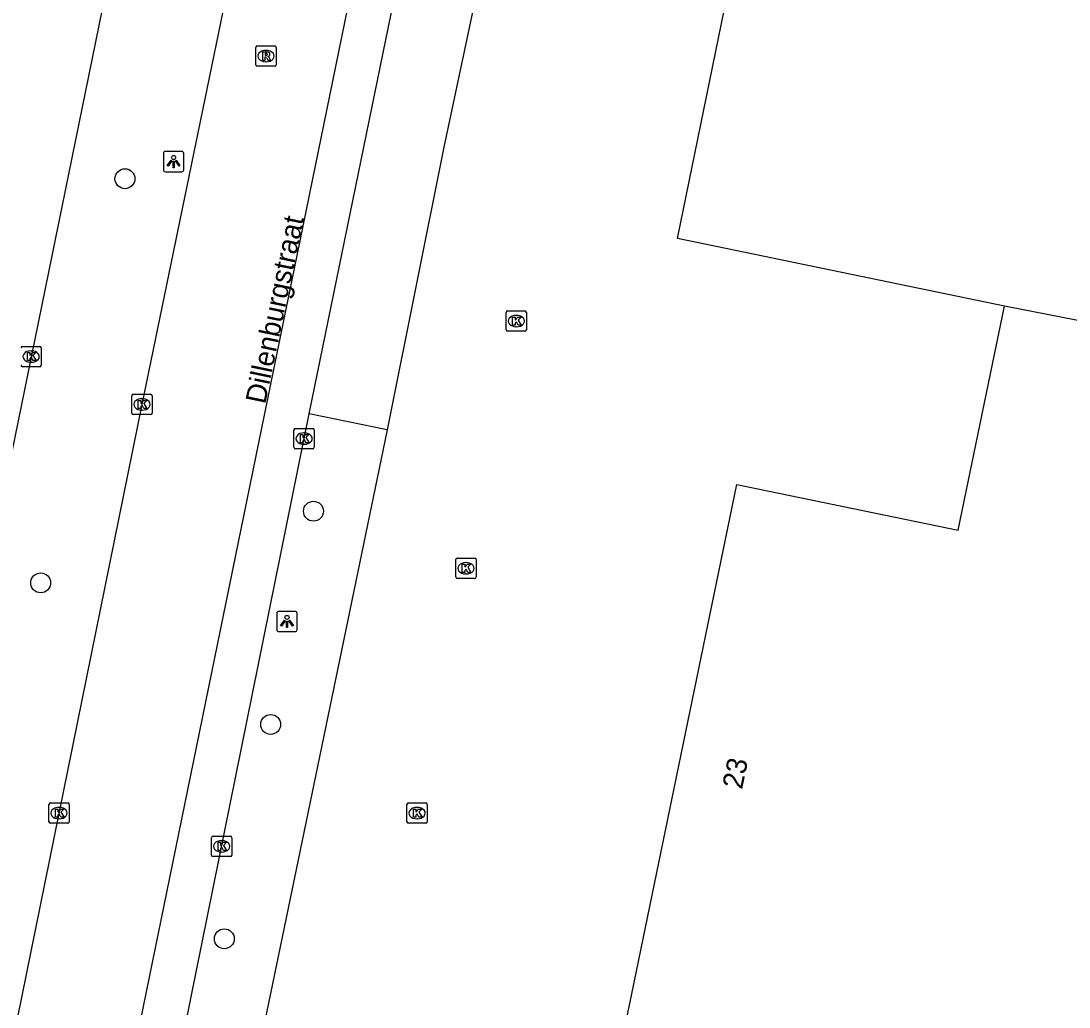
# Model space of a CAD drawing. Extents: x 157692 to 159670, y 381454 to 383289.
# Drawn here: x 158528.9 to 158580.5, y 382137.6 to 382186.1 of the extents above; entities that cross this region are included whole.
import ezdxf

# ---------------------------------------------------------------- set-up
doc = ezdxf.new("R2010")
doc.units = 0
for name, color, linetype in [('IMGEO_Boom', 7, 'Continuous'), ('IMGEO_Kolk', 7, 'Continuous'), ('IMGEO_Lichtpunt', 7, 'Continuous'), ('IMGEO_Openbare_ruimte_label', 7, 'Continuous'), ('IMGEO_Pand', 7, 'Continuous'), ('IMGEO_Pand_nummerreeks', 7, 'Continuous'), ('IMGEO_Rijbaan_lokaal_gesloten', 7, 'Continuous'), ('IMGEO_Rijbaan_lokaal_open', 7, 'Continuous'), ('IMGEO_Rioolput', 7, 'Continuous'), ('IMGEO_Voetpad_open', 7, 'Continuous')]:
    doc.layers.add(name, color=color, linetype=linetype)

msp = doc.modelspace()

# ---------------------------------------------------------------- linework, layer by layer
at = {"layer": 'IMGEO_Boom'}
for centre in [(158534.04, 382178.306), (158543.31, 382161.961), (158529.896, 382158.438), (158541.206, 382151.477), (158538.925, 382140.939)]:
    msp.add_circle(centre, 0.489, dxfattribs=at)
at = {"layer": 'IMGEO_Kolk'}
for p, q in [((158552.783, 382170.882), (158552.783, 382171.734)), ((158552.858, 382171.808), (158553.71, 382171.808)), ((158553.271, 382171.588), (158553.296, 382171.588)), ((158553.784, 382171.734), (158553.784, 382170.882)), ((158553.294, 382171.028), (158553.269, 382171.028)), ((158553.71, 382170.808), (158552.858, 382170.808)), ((158529.001, 382170.064), (158529.853, 382170.064)), ((158529.414, 382169.844), (158529.439, 382169.844)), ((158529.927, 382169.99), (158529.927, 382169.138)), ((158529.853, 382169.064), (158529.001, 382169.064)), ((158529.437, 382169.284), (158529.412, 382169.284)), ((158534.376, 382166.784), (158534.376, 382167.636)), ((158534.451, 382167.71), (158535.303, 382167.71)), ((158534.864, 382167.49), (158534.889, 382167.49)), ((158535.377, 382167.636), (158535.377, 382166.784)), ((158534.887, 382166.93), (158534.862, 382166.93)), ((158535.303, 382166.71), (158534.451, 382166.71)), ((158542.351, 382165.104), (158542.351, 382165.956)), ((158542.426, 382166.03), (158543.278, 382166.03)), ((158543.352, 382165.956), (158543.352, 382165.104)), ((158542.839, 382165.81), (158542.864, 382165.81)), ((158543.278, 382165.03), (158542.426, 382165.03)), ((158542.862, 382165.25), (158542.837, 382165.25)), ((158550.31, 382158.728), (158550.31, 382159.58)), ((158550.385, 382159.654), (158551.237, 382159.654)), ((158550.798, 382159.434), (158550.823, 382159.434)), ((158551.311, 382159.58), (158551.311, 382158.728)), ((158551.237, 382158.654), (158550.385, 382158.654)), ((158550.821, 382158.874), (158550.796, 382158.874)), ((158530.299, 382146.692), (158530.299, 382147.544)), ((158530.374, 382147.618), (158531.226, 382147.618)), ((158530.787, 382147.398), (158530.812, 382147.398)), ((158531.3, 382147.544), (158531.3, 382146.692)), ((158547.907, 382146.691), (158547.907, 382147.543)), ((158547.982, 382147.617), (158548.834, 382147.617)), ((158548.395, 382147.397), (158548.42, 382147.397)), ((158548.908, 382147.543), (158548.908, 382146.691)), ((158530.81, 382146.838), (158530.785, 382146.838)), ((158548.418, 382146.837), (158548.393, 382146.837)), ((158531.226, 382146.618), (158530.374, 382146.618)), ((158548.834, 382146.617), (158547.982, 382146.617)), ((158538.297, 382145.058), (158538.297, 382145.91)), ((158538.372, 382145.984), (158539.224, 382145.984)), ((158539.298, 382145.91), (158539.298, 382145.058)), ((158538.785, 382145.764), (158538.81, 382145.764)), ((158539.224, 382144.984), (158538.372, 382144.984)), ((158538.808, 382145.204), (158538.783, 382145.204))]:
    msp.add_line(p, q, dxfattribs=at)
for points in [[(158552.783, 382170.882), (158552.783, 382171.734)], [(158552.858, 382171.808), (158553.71, 382171.808)], [(158553.784, 382171.734), (158553.784, 382170.882)], [(158553.104, 382171.508), (158553.227, 382171.508), (158553.227, 382171.357), (158553.357, 382171.508), (158553.521, 382171.508), (158553.375, 382171.357), (158553.528, 382171.108), (158553.376, 382171.108), (158553.291, 382171.272), (158553.227, 382171.205), (158553.227, 382171.108), (158553.104, 382171.108), (158553.104, 382171.508)], [(158553.71, 382170.808), (158552.858, 382170.808)], [(158529.001, 382170.064), (158529.853, 382170.064)], [(158529.247, 382169.764), (158529.37, 382169.764), (158529.37, 382169.613), (158529.5, 382169.764), (158529.664, 382169.764), (158529.518, 382169.613), (158529.671, 382169.364), (158529.519, 382169.364), (158529.434, 382169.528), (158529.37, 382169.461), (158529.37, 382169.364), (158529.247, 382169.364), (158529.247, 382169.764)], [(158529.927, 382169.99), (158529.927, 382169.138)], [(158529.853, 382169.064), (158529.001, 382169.064)], [(158534.376, 382166.784), (158534.376, 382167.636)], [(158534.451, 382167.71), (158535.303, 382167.71)], [(158535.377, 382167.636), (158535.377, 382166.784)], [(158534.697, 382167.41), (158534.82, 382167.41), (158534.82, 382167.259), (158534.95, 382167.41), (158535.114, 382167.41), (158534.968, 382167.259), (158535.121, 382167.01), (158534.969, 382167.01), (158534.884, 382167.174), (158534.82, 382167.107), (158534.82, 382167.01), (158534.697, 382167.01), (158534.697, 382167.41)], [(158535.303, 382166.71), (158534.451, 382166.71)], [(158542.351, 382165.104), (158542.351, 382165.956)], [(158542.426, 382166.03), (158543.278, 382166.03)], [(158543.352, 382165.956), (158543.352, 382165.104)], [(158542.672, 382165.73), (158542.795, 382165.73), (158542.795, 382165.579), (158542.925, 382165.73), (158543.089, 382165.73), (158542.943, 382165.579), (158543.096, 382165.33), (158542.944, 382165.33), (158542.859, 382165.494), (158542.795, 382165.427), (158542.795, 382165.33), (158542.672, 382165.33), (158542.672, 382165.73)], [(158543.278, 382165.03), (158542.426, 382165.03)], [(158550.31, 382158.728), (158550.31, 382159.58)], [(158550.385, 382159.654), (158551.237, 382159.654)], [(158550.631, 382159.354), (158550.754, 382159.354), (158550.754, 382159.203), (158550.884, 382159.354), (158551.048, 382159.354), (158550.902, 382159.203), (158551.055, 382158.954), (158550.903, 382158.954), (158550.818, 382159.118), (158550.754, 382159.051), (158550.754, 382158.954), (158550.631, 382158.954), (158550.631, 382159.354)], [(158551.311, 382159.58), (158551.311, 382158.728)], [(158551.237, 382158.654), (158550.385, 382158.654)], [(158530.299, 382146.692), (158530.299, 382147.544)], [(158530.374, 382147.618), (158531.226, 382147.618)], [(158530.62, 382147.318), (158530.743, 382147.318), (158530.743, 382147.167), (158530.873, 382147.318), (158531.037, 382147.318), (158530.891, 382147.167), (158531.044, 382146.918), (158530.892, 382146.918), (158530.807, 382147.082), (158530.743, 382147.015), (158530.743, 382146.918), (158530.62, 382146.918), (158530.62, 382147.318)], [(158531.3, 382147.544), (158531.3, 382146.692)], [(158547.907, 382146.691), (158547.907, 382147.543)], [(158547.982, 382147.617), (158548.834, 382147.617)], [(158548.228, 382147.317), (158548.351, 382147.317), (158548.351, 382147.166), (158548.481, 382147.317), (158548.645, 382147.317), (158548.499, 382147.166), (158548.652, 382146.917), (158548.5, 382146.917), (158548.415, 382147.081), (158548.351, 382147.014), (158548.351, 382146.917), (158548.228, 382146.917), (158548.228, 382147.317)], [(158548.908, 382147.543), (158548.908, 382146.691)], [(158531.226, 382146.618), (158530.374, 382146.618)], [(158548.834, 382146.617), (158547.982, 382146.617)], [(158538.297, 382145.058), (158538.297, 382145.91)], [(158538.372, 382145.984), (158539.224, 382145.984)], [(158539.298, 382145.91), (158539.298, 382145.058)], [(158538.618, 382145.684), (158538.741, 382145.684), (158538.741, 382145.533), (158538.871, 382145.684), (158539.035, 382145.684), (158538.889, 382145.533), (158539.042, 382145.284), (158538.89, 382145.284), (158538.805, 382145.448), (158538.741, 382145.381), (158538.741, 382145.284), (158538.618, 382145.284), (158538.618, 382145.684)], [(158539.224, 382144.984), (158538.372, 382144.984)]]:
    msp.add_lwpolyline(points, dxfattribs=at)
for centre, start, end in [((158552.86, 382171.732), 91.552, 178.448), ((158552.86, 382171.732), 91.552, 178.448), ((158553.708, 382171.732), 1.552, 88.448), ((158553.708, 382171.732), 1.552, 88.448), ((158552.86, 382170.884), 181.552, 268.448), ((158552.86, 382170.884), 181.552, 268.448), ((158553.708, 382170.884), 271.552, 358.448), ((158553.708, 382170.884), 271.552, 358.448), ((158529.003, 382169.988), 91.552, 178.448), ((158529.003, 382169.988), 91.552, 178.448), ((158529.851, 382169.988), 1.552, 88.448), ((158529.851, 382169.988), 1.552, 88.448), ((158529.003, 382169.14), 181.552, 268.448), ((158529.003, 382169.14), 181.552, 268.448), ((158529.851, 382169.14), 271.552, 358.448), ((158529.851, 382169.14), 271.552, 358.448), ((158534.453, 382167.634), 91.552, 178.448), ((158534.453, 382167.634), 91.552, 178.448), ((158535.301, 382167.634), 1.552, 88.448), ((158535.301, 382167.634), 1.552, 88.448), ((158534.453, 382166.786), 181.552, 268.448), ((158534.453, 382166.786), 181.552, 268.448), ((158535.301, 382166.786), 271.552, 358.448), ((158535.301, 382166.786), 271.552, 358.448), ((158542.428, 382165.954), 91.552, 178.448), ((158542.428, 382165.954), 91.552, 178.448), ((158543.276, 382165.954), 1.552, 88.448), ((158543.276, 382165.954), 1.552, 88.448), ((158542.428, 382165.106), 181.552, 268.448), ((158542.428, 382165.106), 181.552, 268.448), ((158543.276, 382165.106), 271.552, 358.448), ((158543.276, 382165.106), 271.552, 358.448), ((158550.387, 382159.578), 91.552, 178.448), ((158550.387, 382159.578), 91.552, 178.448), ((158551.235, 382159.578), 1.552, 88.448), ((158551.235, 382159.578), 1.552, 88.448), ((158550.387, 382158.73), 181.552, 268.448), ((158550.387, 382158.73), 181.552, 268.448), ((158551.235, 382158.73), 271.552, 358.448), ((158551.235, 382158.73), 271.552, 358.448), ((158530.376, 382147.542), 91.552, 178.448), ((158530.376, 382147.542), 91.552, 178.448), ((158531.224, 382147.542), 1.552, 88.448), ((158531.224, 382147.542), 1.552, 88.448), ((158547.984, 382147.541), 91.552, 178.448), ((158547.984, 382147.541), 91.552, 178.448), ((158548.832, 382147.541), 1.552, 88.448), ((158548.832, 382147.541), 1.552, 88.448), ((158530.376, 382146.694), 181.552, 268.448), ((158530.376, 382146.694), 181.552, 268.448), ((158531.224, 382146.694), 271.552, 358.448), ((158531.224, 382146.694), 271.552, 358.448), ((158547.984, 382146.693), 181.552, 268.448), ((158547.984, 382146.693), 181.552, 268.448), ((158548.832, 382146.693), 271.552, 358.448), ((158548.832, 382146.693), 271.552, 358.448), ((158538.374, 382145.908), 91.552, 178.448), ((158538.374, 382145.908), 91.552, 178.448), ((158539.222, 382145.908), 1.552, 88.448), ((158539.222, 382145.908), 1.552, 88.448), ((158538.374, 382145.06), 181.552, 268.448), ((158538.374, 382145.06), 181.552, 268.448), ((158539.222, 382145.06), 271.552, 358.448), ((158539.222, 382145.06), 271.552, 358.448)]:
    msp.add_arc(centre, 0.0765, start, end, dxfattribs=at)
for centre, major_axis, ratio, start_param, end_param in [((158553.27, 382171.308), (-0.387, 0.002), 0.722429, 4.712389, 7.853982), ((158553.295, 382171.308), (-0.39, 0.002), 0.717154, 1.570796, 4.712389), ((158529.413, 382169.564), (-0.387, 0.002), 0.722429, 4.712389, 7.853982), ((158529.438, 382169.564), (-0.39, 0.002), 0.717154, 1.570796, 4.712389), ((158534.863, 382167.21), (-0.387, 0.002), 0.722429, 4.712389, 7.853982), ((158534.888, 382167.21), (-0.39, 0.002), 0.717154, 1.570796, 4.712389), ((158542.838, 382165.53), (-0.387, 0.002), 0.722429, 4.712389, 7.853982), ((158542.863, 382165.53), (-0.39, 0.002), 0.717154, 1.570796, 4.712389), ((158550.797, 382159.154), (-0.387, 0.002), 0.722429, 4.712389, 7.853982), ((158550.822, 382159.154), (-0.39, 0.002), 0.717154, 1.570796, 4.712389), ((158530.786, 382147.118), (-0.387, 0.002), 0.722429, 4.712389, 7.853982), ((158530.811, 382147.118), (-0.39, 0.002), 0.717154, 1.570796, 4.712389), ((158548.394, 382147.117), (-0.387, 0.002), 0.722429, 4.712389, 7.853982), ((158548.419, 382147.117), (-0.39, 0.002), 0.717154, 1.570796, 4.712389), ((158538.784, 382145.484), (-0.387, 0.002), 0.722429, 4.712389, 7.853982), ((158538.809, 382145.484), (-0.39, 0.002), 0.717154, 1.570796, 4.712389)]:
    msp.add_ellipse(centre, major_axis=major_axis, ratio=ratio, start_param=start_param, end_param=end_param, dxfattribs=at)
at = {"layer": 'IMGEO_Lichtpunt'}
for p, q in [((158535.933, 382179.553), (158535.933, 382178.746)), ((158535.933, 382179.553), (158535.933, 382178.746)), ((158536.835, 382179.648), (158536.027, 382179.648)), ((158536.835, 382179.648), (158536.027, 382179.648)), ((158536.929, 382178.746), (158536.929, 382179.553)), ((158536.929, 382178.746), (158536.929, 382179.553)), ((158536.027, 382178.652), (158536.835, 382178.652)), ((158536.027, 382178.652), (158536.835, 382178.652)), ((158541.51, 382156.942), (158541.51, 382156.135)), ((158541.51, 382156.942), (158541.51, 382156.135)), ((158542.412, 382157.037), (158541.604, 382157.037)), ((158542.412, 382157.037), (158541.604, 382157.037)), ((158542.506, 382156.135), (158542.506, 382156.942)), ((158542.506, 382156.135), (158542.506, 382156.942)), ((158541.604, 382156.041), (158542.412, 382156.041)), ((158541.604, 382156.041), (158542.412, 382156.041))]:
    msp.add_line(p, q, dxfattribs=at)
for points in [[(158536.307, 382179.217), (158536.346, 382179.189), (158536.158, 382178.927), (158536.12, 382178.954), (158536.307, 382179.217)], [(158536.409, 382179.169), (158536.456, 382179.169), (158536.456, 382178.847), (158536.409, 382178.847), (158536.409, 382179.169)], [(158536.519, 382179.189), (158536.557, 382179.216), (158536.744, 382178.954), (158536.705, 382178.926), (158536.519, 382179.189)], [(158541.884, 382156.606), (158541.923, 382156.578), (158541.735, 382156.316), (158541.697, 382156.343), (158541.884, 382156.606)], [(158542.096, 382156.578), (158542.134, 382156.605), (158542.321, 382156.343), (158542.282, 382156.315), (158542.096, 382156.578)], [(158541.986, 382156.558), (158542.033, 382156.558), (158542.033, 382156.236), (158541.986, 382156.236), (158541.986, 382156.558)]]:
    msp.add_lwpolyline(points, dxfattribs=at)
for centre in [(158536.432, 382179.351), (158542.009, 382156.74)]:
    msp.add_circle(centre, 0.0994, dxfattribs=at)
for centre, start, end in [((158536.027, 382179.553), 90, 180), ((158536.027, 382179.553), 90, 180), ((158536.835, 382179.553), 0, 90), ((158536.835, 382179.553), 0, 90), ((158536.027, 382178.746), 180, 270), ((158536.027, 382178.746), 180, 270), ((158536.835, 382178.746), 270, 0), ((158536.835, 382178.746), 270, 360), ((158541.604, 382156.942), 90, 180), ((158541.604, 382156.942), 90, 180), ((158542.412, 382156.942), 0, 90), ((158542.412, 382156.942), 0, 90), ((158541.604, 382156.135), 180, 270), ((158541.604, 382156.135), 180, 270), ((158542.412, 382156.135), 270, 0), ((158542.412, 382156.135), 270, 360)]:
    msp.add_arc(centre, 0.0946, start, end, dxfattribs=at)
at = {"layer": 'IMGEO_Pand'}
for points in [[(158577.294, 382172.047), (158561.216, 382175.361), (158565.247, 382195.087), (158556.948, 382196.783), (158558.961, 382206.635)], [(158563.223, 382131.236), (158563.315, 382131.7), (158554.772, 382133.456), (158554.818, 382133.659), (158556.568, 382133.298), (158557.225, 382136.428), (158558.548, 382136.172), (158564.131, 382163.272), (158575.023, 382161.028), (158577.294, 382172.047)], [(158617.909, 382164.108), (158577.294, 382172.047)]]:
    msp.add_lwpolyline(points, dxfattribs=at)
at = {"layer": 'IMGEO_Rijbaan_lokaal_gesloten'}
for points in [[(158522.982, 382137.975), (158549.349, 382267.06), (158553.124, 382285.066), (158561.45, 382326.139), (158561.609, 382326.746), (158561.897, 382327.314), (158562.266, 382327.772), (158562.742, 382328.162), (158563.281, 382328.442), (158563.854, 382328.604), (158564.425, 382328.647), (158564.939, 382328.591), (158565.051, 382328.557)], [(158566.644, 382322.187), (158547.202, 382227.455), (158542.075, 382202.135), (158534.877, 382167.21), (158528.747, 382136.998)], [(158563.237, 382275.98), (158554.178, 382231.666), (158544.988, 382186.707), (158534.64, 382136.161)], [(158543.098, 382166.746), (158549.561, 382198.266)], [(158537.008, 382136.63), (158543.098, 382166.746)]]:
    msp.add_lwpolyline(points, dxfattribs=at)
at = {"layer": 'IMGEO_Rijbaan_lokaal_open'}
for points in [[(158553.461, 382197.47), (158549.725, 382179.858), (158546.937, 382165.963)], [(158546.937, 382165.963), (158543.098, 382166.746)]]:
    msp.add_lwpolyline(points, dxfattribs=at)
at = {"layer": 'IMGEO_Rioolput'}
for p, q in [((158540.475, 382183.91), (158540.475, 382184.762)), ((158540.55, 382184.836), (158541.402, 382184.836)), ((158540.963, 382184.616), (158540.988, 382184.616)), ((158541.476, 382184.762), (158541.476, 382183.91)), ((158540.986, 382184.056), (158540.961, 382184.056)), ((158541.402, 382183.836), (158540.55, 382183.836))]:
    msp.add_line(p, q, dxfattribs=at)
for points in [[(158540.475, 382183.91), (158540.475, 382184.762)], [(158540.55, 382184.836), (158541.402, 382184.836)], [(158541.064, 382184.534), (158540.812, 382184.536), (158540.812, 382184.136)], [(158540.99, 382184.455), (158540.936, 382184.455), (158540.936, 382184.374)], [(158541.476, 382184.762), (158541.476, 382183.91)], [(158540.812, 382184.136), (158540.936, 382184.136), (158540.936, 382184.298), (158540.947, 382184.298)], [(158540.936, 382184.374), (158540.988, 382184.374)], [(158540.994, 382184.269), (158541.065, 382184.136), (158541.205, 382184.136), (158541.14, 382184.262)], [(158541.402, 382183.836), (158540.55, 382183.836)]]:
    msp.add_lwpolyline(points, dxfattribs=at)
for centre, radius, start, end in [((158540.552, 382184.76), 0.0765, 91.552, 178.448), ((158540.552, 382184.76), 0.0765, 91.552, 178.448), ((158540.996, 382184.359), 0.0964, 77.0061, 93.1865), ((158541.01, 382184.416), 0.0378, 276.6634, 79.6772), ((158541.063, 382184.424), 0.109, 350.3612, 89.416), ((158541.4, 382184.76), 0.0765, 1.552, 88.448), ((158541.4, 382184.76), 0.0765, 1.552, 88.448), ((158540.552, 382183.912), 0.0765, 181.552, 268.448), ((158540.552, 382183.912), 0.0765, 181.552, 268.448), ((158540.946, 382184.245), 0.0533, 26.0293, 88.6989), ((158540.972, 382184.563), 0.19, 274.7715, 282.9687), ((158541.061, 382184.424), 0.112, 277.5842, 350.9817), ((158541.045, 382184.209), 0.108, 29.5134, 73.7905), ((158541.4, 382183.912), 0.0765, 271.552, 358.448), ((158541.4, 382183.912), 0.0765, 271.552, 358.448)]:
    msp.add_arc(centre, radius, start, end, dxfattribs=at)
for centre, major_axis, ratio, start_param, end_param in [((158540.962, 382184.336), (-0.387, 0.002), 0.722429, 4.712389, 7.853982), ((158540.987, 382184.336), (-0.39, 0.002), 0.717154, 1.570796, 4.712389)]:
    msp.add_ellipse(centre, major_axis=major_axis, ratio=ratio, start_param=start_param, end_param=end_param, dxfattribs=at)
at = {"layer": 'IMGEO_Voetpad_open'}
msp.add_lwpolyline([(158546.937, 382165.963), (158540.709, 382135.881)], dxfattribs=at)

# ---------------------------------------------------------------- texts
at = {"layer": 'IMGEO_Openbare_ruimte_label'}
msp.add_text('Dillenburgstraat', height=1, rotation=78.2855, dxfattribs=at).set_placement((158540.938, 382167.192))
at = {"layer": 'IMGEO_Pand_nummerreeks'}
msp.add_text('23', height=1, rotation=78.3591, dxfattribs=at).set_placement((158564.386, 382148.254))

doc.saveas('drawing.dxf')
